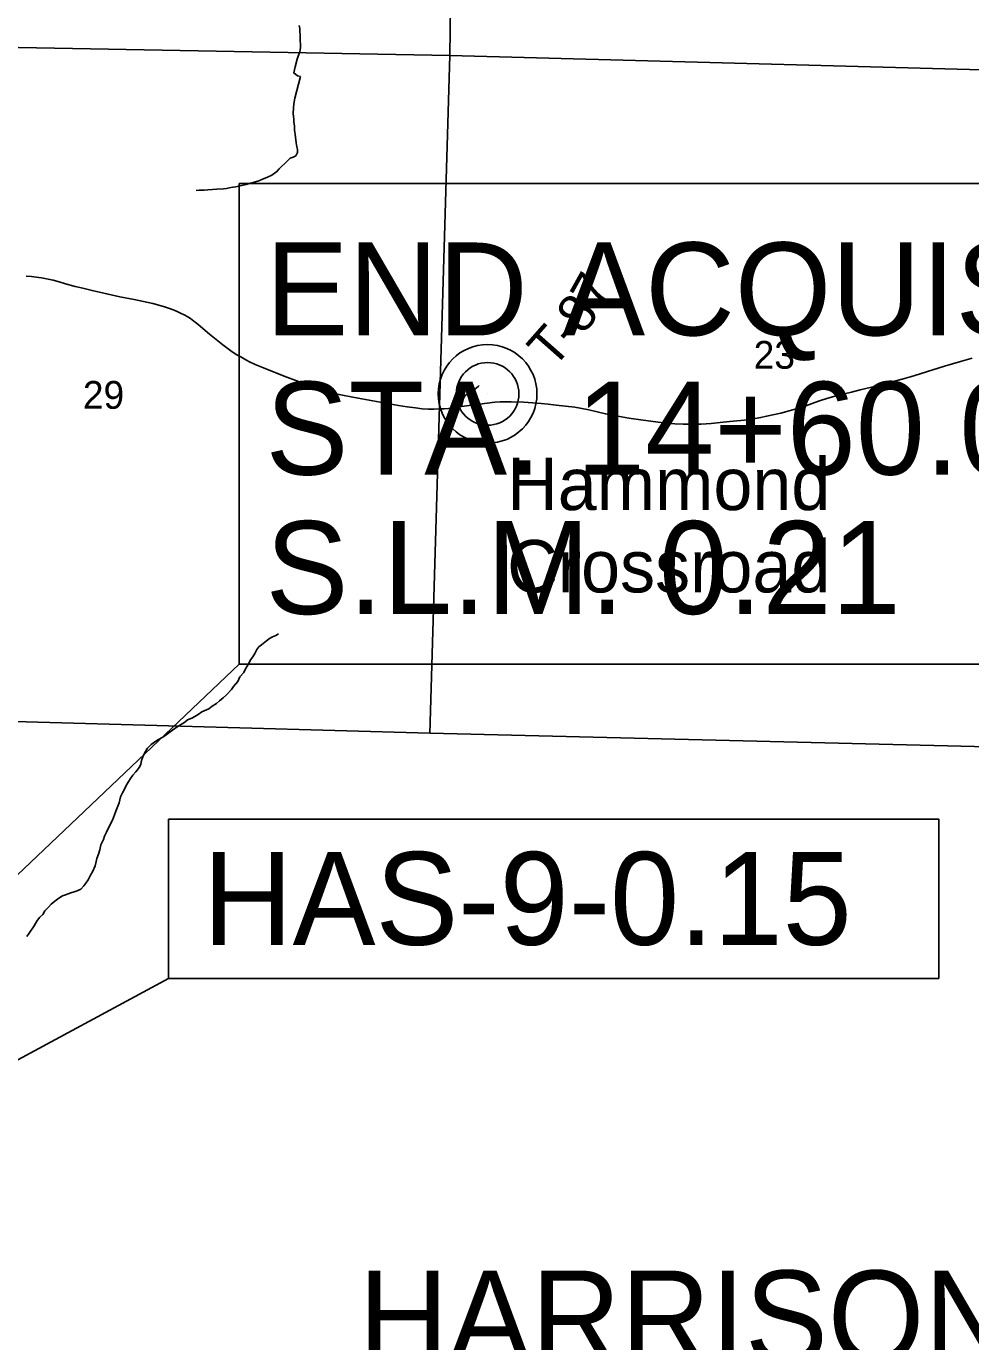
# Model space of a CAD drawing. Extents: x 0 to 34, y 0 to 22.
# Drawn here: x 6.653 to 8.076, y 16.635 to 18.617 of the extents above; entities that cross this region are included whole.
import ezdxf

# ---------------------------------------------------------------- set-up
doc = ezdxf.new("R2010")
doc.units = 0
for name, color, linetype in [('GM_X_Corporation', 7, 'Continuous'), ('GM_X_Minor_River', 7, 'Continuous'), ('GM_X_Section_Text', 7, 'Continuous'), ('GM_X_State_Route', 7, 'Continuous'), ('GM_X_Township_Road', 7, 'Continuous'), ('GM_X_Township_Road_Text', 7, 'Continuous'), ('GM_X_Unincorporated', 7, 'Continuous'), ('GM_X_Unincorporated_Location', 7, 'Continuous'), ('GM_X_Unincorporated_Text', 7, 'Continuous'), ('SH_Text', 7, 'Continuous')]:
    doc.layers.add(name, color=color, linetype=linetype)

msp = doc.modelspace()

# ---------------------------------------------------------------- linework, layer by layer
at = {"layer": 'GM_X_Corporation'}
for points in [[(6.2913, 19.615), (7.2834, 19.5867), (7.3046, 19.5855), (7.291, 18.5737), (6.2882, 18.592)], [(8.2946, 19.5667), (8.3101, 19.5662), (8.2986, 18.5464), (7.291, 18.5737), (7.3046, 19.5855)], [(6.2734, 18.5913), (6.2882, 18.592), (7.291, 18.5737), (7.261, 17.5518), (6.258, 17.5799)], [(8.2986, 18.5464), (8.2669, 17.5271), (7.261, 17.5518), (7.291, 18.5737)]]:
    msp.add_lwpolyline(points, close=True, dxfattribs=at)
at = {"layer": 'GM_X_Minor_River'}
for points in [[(7.0638, 18.6187), (7.0651, 18.6142), (7.0661, 18.586), (7.0652, 18.5815), (7.0642, 18.5773), (7.0625, 18.5727), (7.0607, 18.5677), (7.0581, 18.5564), (7.0568, 18.5518), (7.0558, 18.5473), (7.0613, 18.5429), (7.0662, 18.542)], [(7.0662, 18.542), (7.0576, 18.5093), (7.056, 18.5006), (7.0554, 18.4945), (7.055, 18.4862), (7.0552, 18.4817), (7.0557, 18.4776), (7.0558, 18.4735), (7.0568, 18.4667), (7.057, 18.4611), (7.058, 18.4551), (7.0586, 18.4502), (7.0596, 18.442), (7.0606, 18.436), (7.0612, 18.4319), (7.0613, 18.427), (7.0588, 18.4224), (7.0547, 18.4204), (7.0506, 18.4187), (7.0459, 18.4144), (7.0337, 18.4027), (7.0305, 18.3985), (7.0227, 18.3929), (7.0164, 18.3901), (7.0078, 18.3864), (7.0029, 18.3847), (6.9946, 18.3822), (6.9905, 18.3809), (6.9841, 18.3792), (6.977, 18.3774), (6.9687, 18.3757), (6.9641, 18.3748), (6.9585, 18.3738), (6.9543, 18.3729), (6.9498, 18.3724), (6.9399, 18.372), (6.9335, 18.3715), (6.9263, 18.3712), (6.9206, 18.3706), (6.9134, 18.3704), (6.9089, 18.3702)], [(6.6534, 17.2456), (6.6567, 17.2502), (6.6646, 17.2614), (6.6685, 17.2687), (6.6725, 17.2738), (6.6773, 17.2785), (6.6805, 17.2843), (6.686, 17.2894), (6.69, 17.294), (6.6955, 17.2987), (6.7015, 17.3031), (6.707, 17.3067), (6.7115, 17.3083), (6.7156, 17.3096), (6.7198, 17.3113), (6.7246, 17.3126), (6.7291, 17.3142), (6.7348, 17.3167), (6.7395, 17.3217), (6.7424, 17.326), (6.7456, 17.331), (6.7492, 17.3379), (6.7531, 17.3441), (6.7562, 17.3521), (6.7579, 17.3586), (6.7589, 17.3632), (6.7613, 17.3693), (6.7634, 17.3758), (6.765, 17.3838), (6.7689, 17.3915), (6.7706, 17.3964), (6.7734, 17.4029), (6.7755, 17.4072), (6.778, 17.4118), (6.7801, 17.416), (6.7826, 17.421), (6.7857, 17.4286), (6.7878, 17.4344), (6.7927, 17.447), (6.7946, 17.4557), (6.7978, 17.4619), (6.8003, 17.4665), (6.8035, 17.4741), (6.8071, 17.4795), (6.8099, 17.4838), (6.8132, 17.4884), (6.8179, 17.4935), (6.823, 17.5008), (6.8251, 17.5051), (6.8264, 17.5108), (6.8281, 17.5161), (6.8306, 17.5218), (6.8352, 17.5292), (6.8407, 17.535), (6.8478, 17.5398), (6.8519, 17.5422), (6.8582, 17.5461), (6.8634, 17.5493), (6.8674, 17.5525), (6.873, 17.5564), (6.88, 17.5612), (6.8874, 17.566), (6.8915, 17.5684), (6.8956, 17.5719), (6.9023, 17.5744), (6.9068, 17.5772), (6.9116, 17.58), (6.9171, 17.5843), (6.9276, 17.5888), (6.9328, 17.5924), (6.9391, 17.5967), (6.9439, 17.6007), (6.9494, 17.6054), (6.9542, 17.6097), (6.9619, 17.6175), (6.9651, 17.6221), (6.9713, 17.6299), (6.9745, 17.6368), (6.9803, 17.6434), (6.9831, 17.6491), (6.9882, 17.6568), (6.9906, 17.6626), (6.9942, 17.6668), (6.9971, 17.6718), (7.0003, 17.678), (7.0032, 17.6822), (7.0073, 17.685), (7.0146, 17.6913), (7.019, 17.6948), (7.0239, 17.6972), (7.0288, 17.6989), (7.0328, 17.7017)]]:
    msp.add_lwpolyline(points, dxfattribs=at)
at = {"layer": 'GM_X_State_Route'}
msp.add_lwpolyline([(6.6523, 18.2409), (6.6602, 18.2402), (6.6677, 18.2394), (6.6754, 18.2383), (6.6855, 18.2364), (6.6933, 18.2346), (6.702, 18.2323), (6.7115, 18.2295), (6.7264, 18.2253), (6.7377, 18.2226), (6.7517, 18.2191), (6.7759, 18.2135), (6.7936, 18.2098), (6.815, 18.2054), (6.8432, 18.1994), (6.8524, 18.1971), (6.8611, 18.1946), (6.8686, 18.1923), (6.8756, 18.1896), (6.8811, 18.1871), (6.8863, 18.1846), (6.8906, 18.1824), (6.8959, 18.1793), (6.9, 18.1768), (6.905, 18.1732), (6.9111, 18.1685), (6.9187, 18.1621), (6.9287, 18.1535), (6.9387, 18.1453), (6.9487, 18.1373), (6.9547, 18.1328), (6.9627, 18.127), (6.9698, 18.1224), (6.9759, 18.119), (6.9834, 18.1148), (6.9893, 18.1116), (6.9974, 18.1079), (7.0101, 18.1026), (7.0286, 18.0951), (7.0453, 18.0887), (7.0723, 18.0785), (7.0897, 18.0721), (7.0973, 18.0695), (7.1041, 18.0672), (7.1118, 18.0652), (7.1218, 18.0629), (7.1319, 18.0609), (7.1531, 18.057), (7.2138, 18.046), (7.2266, 18.0439), (7.2393, 18.0421), (7.2493, 18.0409), (7.2591, 18.0404), (7.2668, 18.0403), (7.2761, 18.0406), (7.2791, 18.0406), (7.2823, 18.0408), (7.2889, 18.0414), (7.3047, 18.0435), (7.3088, 18.0441), (7.3473, 18.0496), (7.3589, 18.0508), (7.367, 18.0513), (7.3742, 18.0515), (7.3834, 18.0514), (7.4023, 18.0508), (7.4163, 18.0497), (7.4289, 18.0487), (7.4394, 18.0477), (7.4516, 18.0464), (7.4654, 18.0448), (7.4795, 18.0431), (7.4877, 18.0417), (7.5005, 18.0391), (7.5255, 18.0334), (7.5445, 18.0298), (7.5609, 18.027), (7.5824, 18.0235), (7.5939, 18.022), (7.6053, 18.0206), (7.6187, 18.0191), (7.6304, 18.0182), (7.6426, 18.0176), (7.67, 18.0179), (7.6852, 18.0189), (7.7029, 18.0206), (7.718, 18.022), (7.7351, 18.0238), (7.7441, 18.025), (7.7516, 18.0263), (7.7597, 18.0279), (7.7685, 18.0296), (7.79, 18.0344), (7.8028, 18.0376), (7.8132, 18.0406), (7.8278, 18.0453), (7.847, 18.0522), (7.8611, 18.0568), (7.8736, 18.0604), (7.8862, 18.0636), (7.8965, 18.0662), (7.9099, 18.0694), (7.9335, 18.075), (7.9558, 18.0808), (7.9763, 18.0866), (7.9905, 18.0907), (8.0017, 18.0941), (8.0366, 18.1052), (8.0609, 18.1122), (8.0786, 18.1174)], dxfattribs=at)
at = {"layer": 'GM_X_Township_Road'}
msp.add_lwpolyline([(7.3088, 18.0441), (7.3101, 18.0502), (7.3116, 18.0566), (7.3123, 18.0581), (7.3132, 18.0593), (7.3143, 18.0607), (7.3155, 18.0618), (7.3169, 18.0629), (7.3244, 18.0675), (7.3288, 18.0706), (7.3336, 18.0746), (7.3351, 18.0758)], dxfattribs=at)
at = {"layer": 'GM_X_Unincorporated'}
for radius in [0.0744, 0.0472]:
    msp.add_circle((7.348, 18.0634), radius, dxfattribs=at)
at = {"layer": 'GM_X_Unincorporated_Location'}
msp.add_line((7.348, 18.0634), (7.348, 18.0634), dxfattribs=at)
at = {"layer": 'SH_Text'}
for p, q in [((6.9735, 17.6557), (6.0054, 16.737)), ((6.8671, 17.1823), (6.0105, 16.7196))]:
    msp.add_line(p, q, dxfattribs=at)
for points in [[(6.9735, 18.3806), (8.6708, 18.3806), (8.6708, 17.6557), (6.9735, 17.6557)], [(6.8671, 17.4223), (6.8671, 17.1823), (8.0282, 17.1823), (8.0282, 17.4223)]]:
    msp.add_lwpolyline(points, close=True, dxfattribs=at)

# ---------------------------------------------------------------- texts
at = {"layer": 'GM_X_Section_Text'}
for s, p in [('23', (7.7491, 18.1013)), ('29', (6.7379, 18.0409))]:
    msp.add_text(s, height=0.04186, rotation=0, dxfattribs=at).set_placement(p)
at = {"layer": 'GM_X_Township_Road_Text'}
for s, rotation, p in [('7', 60.8634, (7.5195, 18.1872)), ('8', 50.9486, (7.4915, 18.1511)), ('T', 48.5964, (7.4464, 18.0997)), ('-', 49.0305, (7.4748, 18.1319))]:
    msp.add_text(s, height=0.0568, rotation=rotation, dxfattribs=at).set_placement(p)
at = {"layer": 'GM_X_Unincorporated_Text'}
for s, p in [('Hammond', (7.3775, 17.8882)), ('Crossroad', (7.3775, 17.7641))]:
    msp.add_text(s, height=0.07898, rotation=0, dxfattribs=at).set_placement(p)
at = {"layer": 'SH_Text'}
for s, p in [('END ACQUISITION', (7.0133, 18.1516)), ('STA. 14+60.00', (7.0133, 17.9416)), ('S.L.M. 0.21', (7.0133, 17.7316)), ('HAS-9-0.15', (6.9189, 17.2328)), ('HARRISON COUNTY', (7.1536, 16.6018))]:
    msp.add_text(s, height=0.14, dxfattribs=at).set_placement(p)

doc.saveas('drawing.dxf')
